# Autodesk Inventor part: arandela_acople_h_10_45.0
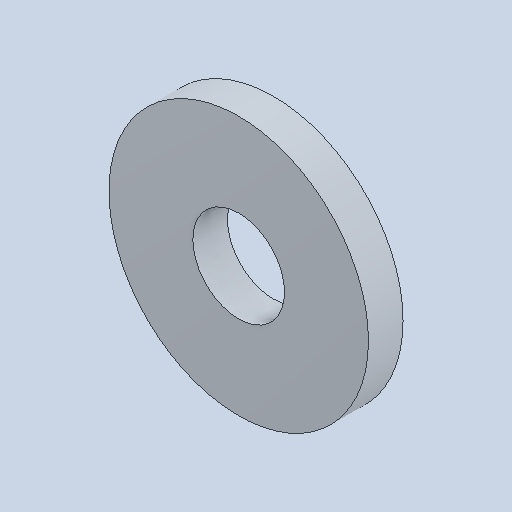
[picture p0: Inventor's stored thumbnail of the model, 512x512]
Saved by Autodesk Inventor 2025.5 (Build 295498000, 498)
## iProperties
Created: 2026-10
Part Number: arandela_acople_h_10_45.0
Material: Genérico
Document SubType Name: Modeling
Designer: Luis M
Density: 1 g/cm^3
Appearance: Valor por defecto
Author: Luis M
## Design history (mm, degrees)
feature "Base1"
node "Sólido1"
